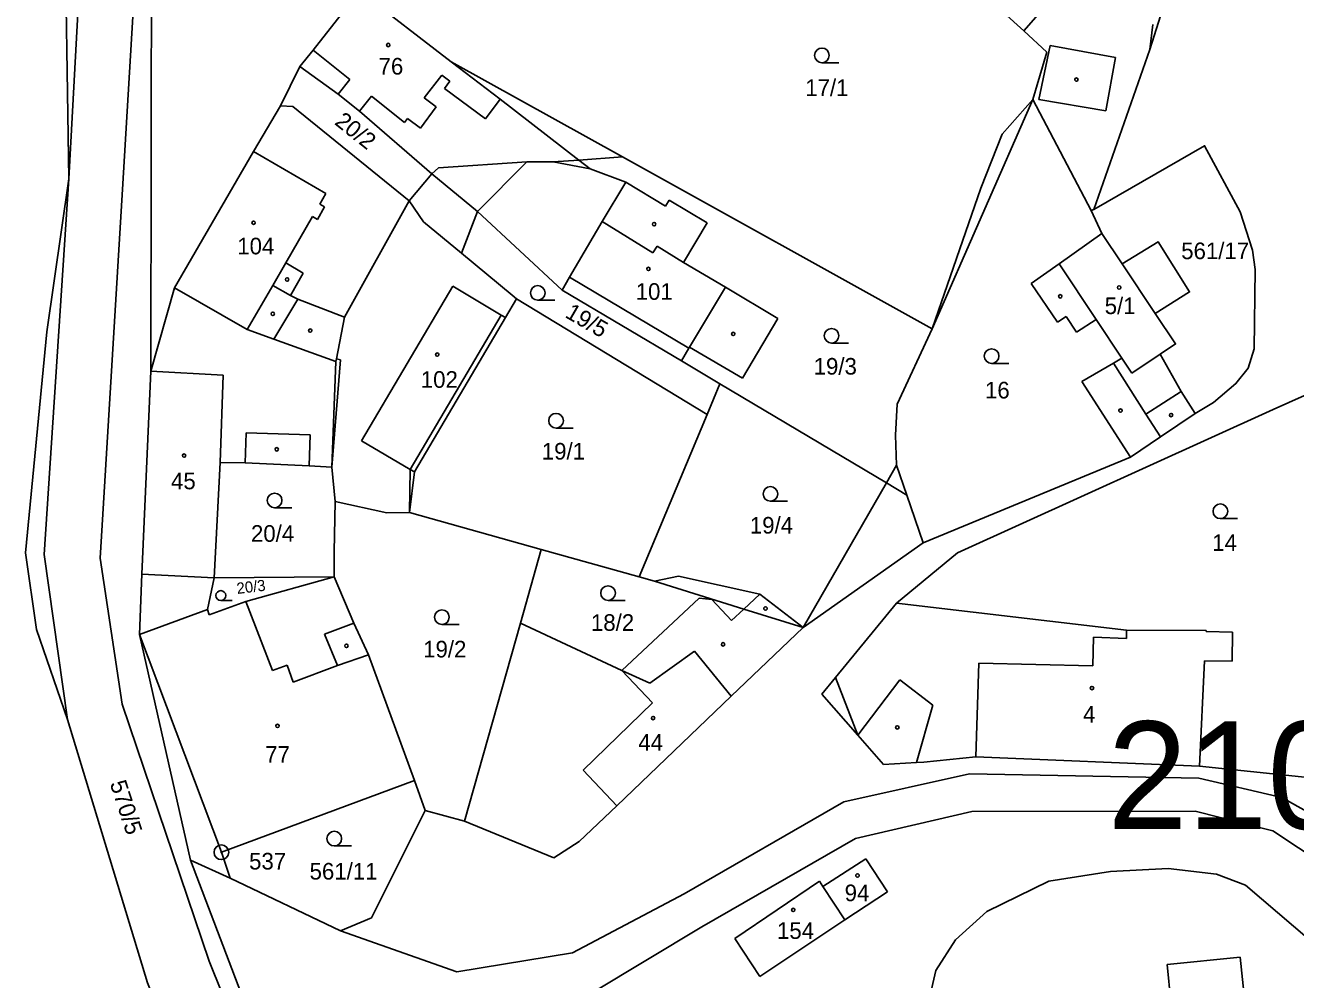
# Model space of a CAD drawing. Extents: x -725765 to -723182, y -1052705 to -1049154.
# Drawn here: x -724819.6 to -724689.6, y -1050869.4 to -1050771.8 of the extents above; entities that cross this region are included whole.
import ezdxf

# ---------------------------------------------------------------- set-up
doc = ezdxf.new("R2010")
doc.units = 0
for name, color, linetype in [('Vrstva 1', 7, 'Continuous'), ('Vrstva 17', 7, 'Continuous'), ('Vrstva 18', 7, 'Continuous'), ('Vrstva 19', 7, 'Continuous'), ('Vrstva 25', 7, 'Continuous'), ('Vrstva 4', 7, 'Continuous'), ('Vrstva 52', 7, 'Continuous'), ('Vrstva 53', 7, 'Continuous')]:
    doc.layers.add(name, color=color, linetype=linetype)

msp = doc.modelspace()

# ---------------------------------------------------------------- linework, layer by layer
at = {"layer": 'Vrstva 1'}
for points in [[(-724815.58, -1050758.85), (-724815.13, -1050787.45)], [(-724728.86, -1050761.96), (-724717.41, -1050772.31)], [(-724806.76, -1050807.12), (-724806.68, -1050763.03)], [(-724704.54, -1050774.22), (-724701.62, -1050765.05)], [(-724790.16, -1050774.29), (-724785.4, -1050768.2)], [(-724785.4, -1050768.2), (-724776.03, -1050775.48)], [(-724717.41, -1050772.31), (-724715.08, -1050774.5)], [(-724791.52, -1050775.96), (-724790.16, -1050774.29)], [(-724716.5, -1050779.33), (-724715.08, -1050774.5)], [(-724710.25, -1050790.58), (-724704.54, -1050774.22)], [(-724793.48, -1050779.98), (-724791.52, -1050775.96)], [(-724791.52, -1050775.96), (-724787.58, -1050778.77)], [(-724776.03, -1050775.48), (-724758.5, -1050785.2)], [(-724787.58, -1050778.77), (-724785.41, -1050780.52)], [(-724796.25, -1050784.66), (-724793.48, -1050779.98)], [(-724793.48, -1050779.98), (-724792.22, -1050780.03)], [(-724792.22, -1050780.03), (-724780.32, -1050789.71)], [(-724726.79, -1050802.8), (-724716.5, -1050779.33)], [(-724716.5, -1050779.33), (-724710.52, -1050790.67)], [(-724785.41, -1050780.52), (-724778, -1050786.94)], [(-724710.25, -1050790.58), (-724698.92, -1050784.06)], [(-724698.92, -1050784.06), (-724695.3, -1050790.82)], [(-724804.34, -1050798.59), (-724796.25, -1050784.66)], [(-724762.96, -1050785.53), (-724758.5, -1050785.2)], [(-724758.5, -1050785.2), (-724726.79, -1050802.8)], [(-724778, -1050786.94), (-724777.32, -1050786.32)], [(-724777.32, -1050786.32), (-724768.27, -1050785.71)], [(-724768.27, -1050785.71), (-724765.6, -1050785.72)], [(-724765.6, -1050785.72), (-724762.96, -1050785.53)], [(-724817.4, -1050803.09), (-724815.13, -1050787.45)], [(-724780.32, -1050789.71), (-724778, -1050786.94)], [(-724778, -1050786.94), (-724773.32, -1050790.79)], [(-724786.93, -1050801.6), (-724780.32, -1050789.71)], [(-724780.32, -1050789.71), (-724778.87, -1050791.83)], [(-724710.52, -1050790.67), (-724710.25, -1050790.58)], [(-724710.52, -1050790.67), (-724709.43, -1050793.04)], [(-724778.87, -1050791.83), (-724774.96, -1050795.04)], [(-724773.32, -1050790.79), (-724764.68, -1050798.83)], [(-724763.91, -1050797.52), (-724760.56, -1050791.82)], [(-724760.56, -1050791.82), (-724755.37, -1050795.02)], [(-724695.3, -1050790.82), (-724694.03, -1050794.75)], [(-724713.82, -1050796.14), (-724709.43, -1050793.04)], [(-724709.43, -1050793.04), (-724707.37, -1050796.13)], [(-724755.37, -1050795.02), (-724754.95, -1050794.32)], [(-724754.95, -1050794.32), (-724752.24, -1050795.99)], [(-724707.37, -1050796.13), (-724703.67, -1050793.89)], [(-724703.67, -1050793.89), (-724700.46, -1050799.01)], [(-724774.96, -1050795.04), (-724769.79, -1050799.33)], [(-724694.03, -1050794.75), (-724693.75, -1050796.73)], [(-724752.24, -1050795.99), (-724747.96, -1050798.54)], [(-724716.67, -1050798.15), (-724713.82, -1050796.14)], [(-724693.85, -1050804.82), (-724693.75, -1050796.73)], [(-724764.68, -1050798.83), (-724763.91, -1050797.52)], [(-724716.67, -1050798.15), (-724713.98, -1050802.11)], [(-724806.76, -1050807.12), (-724804.34, -1050798.59)], [(-724804.34, -1050798.59), (-724796.91, -1050802.85)], [(-724770.47, -1050801.64), (-724769.33, -1050799.71)], [(-724769.79, -1050799.33), (-724769.33, -1050799.71)], [(-724769.33, -1050799.71), (-724749.83, -1050811.55)], [(-724764.68, -1050798.83), (-724752.45, -1050806.06)], [(-724751.62, -1050804.67), (-724747.96, -1050798.54)], [(-724703.97, -1050801.23), (-724700.46, -1050799.01)], [(-724787.77, -1050805.86), (-724786.93, -1050801.6)], [(-724779.79, -1050817.43), (-724770.47, -1050801.64)], [(-724713.98, -1050802.11), (-724713.08, -1050801.52)], [(-724713.08, -1050801.52), (-724712.03, -1050803.14)], [(-724712.03, -1050803.14), (-724710.03, -1050801.83)], [(-724710.03, -1050801.83), (-724707.39, -1050805.79)], [(-724703.97, -1050801.23), (-724701.9, -1050804.33)], [(-724819.59, -1050825.69), (-724817.4, -1050803.09)], [(-724796.91, -1050802.85), (-724794.18, -1050803.83)], [(-724730.4, -1050810.48), (-724726.79, -1050802.8)], [(-724794.18, -1050803.83), (-724787.82, -1050806.12)], [(-724752.45, -1050806.06), (-724751.69, -1050804.78)], [(-724751.69, -1050804.78), (-724751.62, -1050804.67)], [(-724703.46, -1050805.38), (-724701.9, -1050804.33)], [(-724694.47, -1050806.81), (-724693.85, -1050804.82)], [(-724788.22, -1050816.94), (-724787.82, -1050806.12)], [(-724787.82, -1050806.12), (-724787.77, -1050805.86)], [(-724752.45, -1050806.06), (-724748.52, -1050808.4)], [(-724708.25, -1050806.29), (-724707.39, -1050805.79)], [(-724703.46, -1050805.38), (-724701.33, -1050809.2)], [(-724807.68, -1050827.87), (-724806.76, -1050807.12)], [(-724711.49, -1050808.16), (-724708.25, -1050806.29)], [(-724695.72, -1050808.39), (-724694.47, -1050806.81)], [(-724749.83, -1050811.55), (-724748.52, -1050808.4)], [(-724748.52, -1050808.4), (-724731.49, -1050818.54)], [(-724711.49, -1050808.16), (-724706.52, -1050815.92)], [(-724698, -1050810.32), (-724695.72, -1050808.39)], [(-724691.91, -1050811.03), (-724684.21, -1050807.61)], [(-724701.33, -1050809.2), (-724699.88, -1050811.44)], [(-724730.57, -1050813.66), (-724730.4, -1050810.48)], [(-724724.22, -1050825.7), (-724691.91, -1050811.03)], [(-724703.45, -1050813.85), (-724699.88, -1050811.44)], [(-724699.88, -1050811.44), (-724698, -1050810.32)], [(-724756.78, -1050828.16), (-724749.83, -1050811.55)], [(-724730.57, -1050813.66), (-724730.44, -1050816.72)], [(-724706.52, -1050815.92), (-724703.45, -1050813.85)], [(-724800.28, -1050828.24), (-724799.66, -1050816.47)], [(-724799.66, -1050816.47), (-724797.11, -1050816.51)], [(-724797.11, -1050816.51), (-724790.55, -1050816.79)], [(-724727.72, -1050824.69), (-724706.52, -1050815.92)], [(-724790.55, -1050816.79), (-724788.22, -1050816.94)], [(-724788.22, -1050816.94), (-724787.89, -1050820.45)], [(-724780.28, -1050821.58), (-724779.79, -1050817.43)], [(-724730.44, -1050816.72), (-724729.39, -1050819.79)], [(-724731.49, -1050818.54), (-724729.39, -1050819.79)], [(-724788, -1050825.59), (-724787.89, -1050820.45)], [(-724787.89, -1050820.45), (-724782.62, -1050821.61)], [(-724729.39, -1050819.79), (-724727.72, -1050824.69)], [(-724782.62, -1050821.61), (-724780.28, -1050821.58)], [(-724780.28, -1050821.58), (-724766.81, -1050825.35)], [(-724819.59, -1050825.69), (-724818.46, -1050833.53)], [(-724788.01, -1050828.17), (-724788, -1050825.59)], [(-724768.94, -1050832.9), (-724766.81, -1050825.35)], [(-724766.81, -1050825.35), (-724756.78, -1050828.16)], [(-724740.01, -1050833.33), (-724727.72, -1050824.69)], [(-724730.44, -1050830.86), (-724724.22, -1050825.7)], [(-724807.91, -1050834.06), (-724807.68, -1050827.87)], [(-724800.97, -1050831.5), (-724800.28, -1050828.24)], [(-724800.28, -1050828.24), (-724788.01, -1050828.17)], [(-724797.04, -1050830.69), (-724788.01, -1050828.17)], [(-724788.01, -1050828.17), (-724785.98, -1050832.9)], [(-724756.78, -1050828.16), (-724755.22, -1050828.6)], [(-724755.22, -1050828.6), (-724746.07, -1050831.45)], [(-724800.77, -1050832.05), (-724797.04, -1050830.69)], [(-724736.71, -1050838.46), (-724730.44, -1050830.86)], [(-724730.44, -1050830.86), (-724706.93, -1050833.62)], [(-724807.91, -1050834.06), (-724800.97, -1050831.5)], [(-724800.97, -1050831.5), (-724800.77, -1050832.05)], [(-724746.07, -1050831.45), (-724740.01, -1050833.33)], [(-724818.46, -1050833.53), (-724815.27, -1050842.75)], [(-724785.98, -1050832.9), (-724784.48, -1050836.14)], [(-724774.65, -1050853.16), (-724768.94, -1050832.9)], [(-724768.94, -1050832.9), (-724758.55, -1050837.73)], [(-724747.36, -1050840.36), (-724740.01, -1050833.33)], [(-724807.91, -1050834.06), (-724802.7, -1050857.13)], [(-724807.91, -1050834.06), (-724799.54, -1050856.33)], [(-724706.93, -1050833.62), (-724698.75, -1050833.66)], [(-724698.75, -1050833.66), (-724698.75, -1050833.76)], [(-724698.75, -1050833.76), (-724696.08, -1050833.83)], [(-724696.12, -1050836.78), (-724696.08, -1050833.83)], [(-724784.48, -1050836.14), (-724779.79, -1050849)], [(-724755.68, -1050839.02), (-724751.12, -1050835.77)], [(-724751.12, -1050835.77), (-724747.36, -1050840.36)], [(-724699.44, -1050847.52), (-724698.92, -1050836.75)], [(-724698.92, -1050836.75), (-724696.12, -1050836.78)], [(-724758.55, -1050837.73), (-724755.68, -1050839.02)], [(-724738.11, -1050840.16), (-724736.71, -1050838.46)], [(-724759.08, -1050851.58), (-724747.36, -1050840.36)], [(-724738.11, -1050840.16), (-724734.4, -1050844.36)], [(-724815.27, -1050842.75), (-724807.1, -1050869.67)], [(-724734.4, -1050844.36), (-724731.77, -1050847.34)], [(-724727.64, -1050847.12), (-724722.35, -1050846.57)], [(-724722.35, -1050846.57), (-724699.44, -1050847.52)], [(-724731.77, -1050847.34), (-724728.41, -1050847.16)], [(-724728.41, -1050847.16), (-724727.64, -1050847.12)], [(-724699.44, -1050847.52), (-724683.14, -1050849.22)], [(-724799.54, -1050856.33), (-724779.79, -1050849)], [(-724779.79, -1050849), (-724778.67, -1050852.04)], [(-724762.92, -1050855.21), (-724759.08, -1050851.58)], [(-724784.19, -1050863.03), (-724778.67, -1050852.04)], [(-724778.67, -1050852.04), (-724774.65, -1050853.16)], [(-724774.65, -1050853.16), (-724765.52, -1050856.89)], [(-724765.52, -1050856.89), (-724762.92, -1050855.21)], [(-724799.54, -1050856.33), (-724798.63, -1050858.99)], [(-724802.7, -1050857.13), (-724793.87, -1050880.36)], [(-724737.98, -1050859.82), (-724733.58, -1050857.01)], [(-724733.58, -1050857.01), (-724731.37, -1050860.36)], [(-724708.57, -1050858.29), (-724702.67, -1050857.98)], [(-724702.67, -1050857.98), (-724697.7, -1050858.58)], [(-724798.63, -1050858.99), (-724787.36, -1050864.36)], [(-724747, -1050865.14), (-724738.33, -1050859.3)], [(-724738.33, -1050859.3), (-724737.98, -1050859.82)], [(-724721.2, -1050862.37), (-724714.88, -1050859.27)], [(-724714.88, -1050859.27), (-724708.57, -1050858.29)], [(-724697.7, -1050858.58), (-724694.75, -1050859.69)], [(-724737.98, -1050859.82), (-724735.73, -1050863.25)], [(-724735.73, -1050863.25), (-724731.37, -1050860.36)], [(-724694.75, -1050859.69), (-724688.19, -1050865.28)], [(-724787.36, -1050864.36), (-724784.19, -1050863.03)], [(-724744.43, -1050869.03), (-724735.73, -1050863.25)], [(-724724.4, -1050865.28), (-724721.2, -1050862.37)], [(-724747, -1050865.14), (-724744.43, -1050869.03)], [(-724726.42, -1050868.43), (-724724.4, -1050865.28)], [(-724702.77, -1050867.8), (-724695.28, -1050867.04)], [(-724695.28, -1050867.04), (-724694.82, -1050871.61)], [(-724727.89, -1050874.8), (-724726.42, -1050868.43)], [(-724702.77, -1050867.8), (-724702.38, -1050871.62)]]:
    msp.add_lwpolyline(points, dxfattribs=at)
at = {"layer": 'Vrstva 25'}
for points in [[(-724738.09, -1050775.57), (-724736.34, -1050775.57)], [(-724767.16, -1050799.86), (-724765.41, -1050799.86)], [(-724737.1, -1050804.25), (-724735.35, -1050804.25)], [(-724720.72, -1050806.33), (-724718.97, -1050806.33)], [(-724765.29, -1050812.94), (-724763.54, -1050812.94)], [(-724743.35, -1050820.42), (-724741.6, -1050820.42)], [(-724794.09, -1050821.09), (-724792.34, -1050821.09)], [(-724697.31, -1050822.2), (-724695.56, -1050822.2)], [(-724799.59, -1050830.57), (-724798.42, -1050830.57)], [(-724759.97, -1050830.57), (-724758.22, -1050830.57)], [(-724776.97, -1050833.03), (-724775.22, -1050833.03)], [(-724787.98, -1050855.68), (-724786.23, -1050855.68)]]:
    msp.add_lwpolyline(points, dxfattribs=at)
for centre, radius in [((-724782.46, -1050773.76), 0.175), ((-724738.09, -1050774.82), 0.75), ((-724712.04, -1050777.29), 0.175), ((-724796.24, -1050791.94), 0.175), ((-724755.26, -1050792.08), 0.175), ((-724755.84, -1050796.66), 0.175), ((-724792.81, -1050797.74), 0.175), ((-724767.16, -1050799.11), 0.75), ((-724707.67, -1050798.56), 0.175), ((-724713.7, -1050799.46), 0.175), ((-724794.28, -1050801.25), 0.175), ((-724790.44, -1050802.97), 0.175), ((-724747.16, -1050803.31), 0.175), ((-724737.1, -1050803.5), 0.75), ((-724720.72, -1050805.58), 0.75), ((-724777.45, -1050805.42), 0.175), ((-724765.29, -1050812.19), 0.75), ((-724707.53, -1050811.15), 0.175), ((-724702.36, -1050811.61), 0.175), ((-724793.87, -1050815.11), 0.175), ((-724803.35, -1050815.75), 0.175), ((-724743.35, -1050819.67), 0.75), ((-724794.09, -1050820.34), 0.75), ((-724697.31, -1050821.45), 0.75), ((-724799.59, -1050830.07), 0.503), ((-724759.97, -1050829.82), 0.75), ((-724776.97, -1050832.28), 0.75), ((-724743.86, -1050831.39), 0.175), ((-724786.74, -1050835.21), 0.175), ((-724748.2, -1050835.06), 0.175), ((-724710.45, -1050839.53), 0.175), ((-724755.36, -1050842.6), 0.175), ((-724793.79, -1050843.4), 0.175), ((-724730.37, -1050843.56), 0.175), ((-724787.98, -1050854.93), 0.75), ((-724799.54, -1050856.33), 0.75), ((-724799.54, -1050856.33), 0.032), ((-724734.44, -1050858.7), 0.175), ((-724741.02, -1050862.22), 0.175)]:
    msp.add_circle(centre, radius, dxfattribs=at)
at = {"layer": 'Vrstva 4'}
for points in [[(-724815.13, -1050787.45), (-724813.82, -1050762.96)], [(-724809.63, -1050787.94), (-724808.16, -1050763.42)], [(-724717.41, -1050772.31), (-724712.35, -1050766.47)], [(-724704.54, -1050774.22), (-724704.24, -1050771.67)], [(-724790.16, -1050774.29), (-724786.39, -1050777.27)], [(-724715.89, -1050779.34), (-724714.74, -1050773.81)], [(-724714.74, -1050773.81), (-724708.03, -1050775.05)], [(-724709.02, -1050780.49), (-724708.03, -1050775.05)], [(-724776.03, -1050775.48), (-724771, -1050779.29)], [(-724787.58, -1050778.77), (-724786.39, -1050777.27)], [(-724778.79, -1050779.15), (-724776.97, -1050776.85)], [(-724776.97, -1050776.85), (-724776.16, -1050777.47)], [(-724776.71, -1050778.22), (-724776.16, -1050777.47)], [(-724776.71, -1050778.22), (-724772.51, -1050781.3)], [(-724785.41, -1050780.52), (-724784.18, -1050778.99)], [(-724784.18, -1050778.99), (-724780.79, -1050781.69)], [(-724779.17, -1050782.27), (-724777.57, -1050780.09)], [(-724778.79, -1050779.15), (-724777.57, -1050780.09)], [(-724772.51, -1050781.3), (-724771, -1050779.29)], [(-724771, -1050779.29), (-724762.96, -1050785.53)], [(-724719.63, -1050782.88), (-724716.5, -1050779.33)], [(-724715.89, -1050779.34), (-724709.02, -1050780.49)], [(-724780.79, -1050781.69), (-724780.48, -1050781.29)], [(-724780.48, -1050781.29), (-724779.17, -1050782.27)], [(-724721.83, -1050788.39), (-724719.63, -1050782.88)], [(-724796.25, -1050784.66), (-724788.85, -1050788.94)], [(-724773.32, -1050790.79), (-724768.27, -1050785.71)], [(-724765.6, -1050785.72), (-724761.79, -1050786.43)], [(-724762.96, -1050785.53), (-724761.79, -1050786.43)], [(-724761.79, -1050786.43), (-724758.14, -1050787.79)], [(-724817.68, -1050825.87), (-724815.13, -1050787.45)], [(-724811.93, -1050826.26), (-724809.63, -1050787.94)], [(-724760.56, -1050791.82), (-724758.14, -1050787.79)], [(-724758.14, -1050787.79), (-724754.1, -1050790.24)], [(-724789.47, -1050790.02), (-724788.85, -1050788.94)], [(-724726.79, -1050802.8), (-724721.83, -1050788.39)], [(-724789.71, -1050791.59), (-724788.99, -1050790.3)], [(-724789.47, -1050790.02), (-724788.99, -1050790.3)], [(-724754.1, -1050790.24), (-724753.72, -1050789.62)], [(-724753.72, -1050789.62), (-724749.83, -1050791.94)], [(-724792.93, -1050796.04), (-724790.2, -1050791.29)], [(-724790.2, -1050791.29), (-724789.71, -1050791.59)], [(-724774.96, -1050795.04), (-724773.32, -1050790.79)], [(-724752.24, -1050795.99), (-724749.83, -1050791.94)], [(-724794.27, -1050798.37), (-724792.93, -1050796.04)], [(-724792.93, -1050796.04), (-724791.16, -1050797.08)], [(-724792.48, -1050799.37), (-724791.16, -1050797.08)], [(-724713.82, -1050796.14), (-724710.03, -1050801.83)], [(-724707.37, -1050796.13), (-724703.97, -1050801.23)], [(-724796.91, -1050802.85), (-724794.27, -1050798.37)], [(-724794.27, -1050798.37), (-724792.48, -1050799.37)], [(-724785.19, -1050814.23), (-724775.86, -1050798.44)], [(-724775.86, -1050798.44), (-724770.9, -1050801.39)], [(-724763.91, -1050797.52), (-724751.69, -1050804.78)], [(-724794.18, -1050803.83), (-724791.73, -1050799.77)], [(-724792.48, -1050799.37), (-724791.73, -1050799.77)], [(-724791.73, -1050799.77), (-724786.93, -1050801.6)], [(-724747.96, -1050798.54), (-724742.61, -1050801.73)], [(-724780.22, -1050817.18), (-724770.9, -1050801.39)], [(-724770.9, -1050801.39), (-724770.47, -1050801.64)], [(-724746.22, -1050807.85), (-724742.61, -1050801.73)], [(-724751.62, -1050804.67), (-724746.22, -1050807.85)], [(-724788.22, -1050816.94), (-724787.35, -1050805.95)], [(-724787.77, -1050805.86), (-724787.35, -1050805.95)], [(-724707.39, -1050805.79), (-724706.37, -1050807.33)], [(-724706.37, -1050807.33), (-724703.46, -1050805.38)], [(-724806.76, -1050807.12), (-724799.34, -1050807.54)], [(-724799.66, -1050816.47), (-724799.34, -1050807.54)], [(-724708.25, -1050806.29), (-724704.94, -1050811.51)], [(-724704.94, -1050811.51), (-724701.33, -1050809.2)], [(-724704.94, -1050811.51), (-724703.45, -1050813.85)], [(-724797.11, -1050816.51), (-724797, -1050813.43)], [(-724797, -1050813.43), (-724790.45, -1050813.64)], [(-724790.55, -1050816.79), (-724790.45, -1050813.64)], [(-724785.19, -1050814.23), (-724780.22, -1050817.18)], [(-724780.28, -1050821.58), (-724780.22, -1050817.18)], [(-724780.22, -1050817.18), (-724779.79, -1050817.43)], [(-724731.49, -1050818.54), (-724730.44, -1050816.72)], [(-724740.01, -1050833.33), (-724731.49, -1050818.54)], [(-724817.68, -1050825.87), (-724815.27, -1050842.75)], [(-724811.93, -1050826.26), (-724809.69, -1050841.19)], [(-724807.68, -1050827.87), (-724800.28, -1050828.24)], [(-724755.22, -1050828.6), (-724752.75, -1050828.08)], [(-724752.75, -1050828.08), (-724744.44, -1050829.94)], [(-724797.04, -1050830.69), (-724794.32, -1050837.75)], [(-724758.55, -1050837.73), (-724750.66, -1050830.33)], [(-724750.66, -1050830.33), (-724749.36, -1050830.47)], [(-724749.36, -1050830.47), (-724747.34, -1050832.62)], [(-724746.07, -1050831.45), (-724744.44, -1050829.94)], [(-724744.44, -1050829.94), (-724740.01, -1050833.33)], [(-724747.34, -1050832.62), (-724746.07, -1050831.45)], [(-724788.97, -1050834.02), (-724785.98, -1050832.9)], [(-724788.97, -1050834.02), (-724787.67, -1050837.24)], [(-724710.37, -1050837.27), (-724710.3, -1050834.34)], [(-724710.3, -1050834.34), (-724706.93, -1050834.47)], [(-724706.93, -1050834.47), (-724706.93, -1050833.62)], [(-724787.67, -1050837.24), (-724784.48, -1050836.14)], [(-724794.32, -1050837.75), (-724792.82, -1050837.2)], [(-724792.82, -1050837.2), (-724792.19, -1050838.93)], [(-724792.19, -1050838.93), (-724787.67, -1050837.24)], [(-724722.35, -1050846.57), (-724722.04, -1050837)], [(-724722.04, -1050837), (-724710.37, -1050837.27)], [(-724758.55, -1050837.73), (-724755.41, -1050841.05)], [(-724736.71, -1050838.46), (-724734.4, -1050844.36)], [(-724734.4, -1050844.36), (-724730.12, -1050838.69)], [(-724730.12, -1050838.69), (-724726.72, -1050841.29)], [(-724809.69, -1050841.19), (-724800.77, -1050867.46)], [(-724762.53, -1050847.92), (-724755.41, -1050841.05)], [(-724728.41, -1050847.16), (-724726.72, -1050841.29)], [(-724762.53, -1050847.92), (-724759.08, -1050851.58)], [(-724735.84, -1050851.18), (-724722.97, -1050848.3)], [(-724722.97, -1050848.3), (-724699.53, -1050848.74)], [(-724699.53, -1050848.74), (-724691.02, -1050850.72)], [(-724752.19, -1050860.57), (-724735.84, -1050851.18)], [(-724691.02, -1050850.72), (-724683.3, -1050855.06)], [(-724734.65, -1050854.92), (-724722.73, -1050852.15)], [(-724722.73, -1050852.15), (-724699.9, -1050852.11)], [(-724699.9, -1050852.11), (-724691.95, -1050854.12)], [(-724691.95, -1050854.12), (-724686.7, -1050857.6)], [(-724750.38, -1050863.96), (-724734.65, -1050854.92)], [(-724802.7, -1050857.13), (-724798.63, -1050858.99)], [(-724763.6, -1050866.6), (-724752.19, -1050860.57)], [(-724787.36, -1050864.36), (-724775.43, -1050868.55)], [(-724761.65, -1050870.74), (-724750.38, -1050863.96)], [(-724775.43, -1050868.55), (-724763.6, -1050866.6)], [(-724800.77, -1050867.46), (-724786.35, -1050903.34)]]:
    msp.add_lwpolyline(points, dxfattribs=at)
at = {"layer": 'Vrstva 52'}
for points in [[(-724813.33, -1050644), (-724808.37, -1050650.73), (-724806.43, -1050654.63), (-724804.75, -1050661.51), (-724810.21, -1050691.79), (-724815, -1050731.09), (-724815.58, -1050758.85), (-724815.13, -1050787.45), (-724817.4, -1050803.09), (-724819.59, -1050825.69), (-724818.46, -1050833.53), (-724815.27, -1050842.75), (-724807.1, -1050869.67), (-724799.84, -1050887.62), (-724790.58, -1050905.75), (-724781.27, -1050921.4), (-724774.72, -1050931.91), (-724769.97, -1050937.91), (-724755.76, -1050950.09), (-724747.39, -1050955.27), (-724740.23, -1050960.06), (-724733.48, -1050964.31), (-724729, -1050967.94)], [(-724797.81, -1050648.79), (-724786.08, -1050660.92), (-724787.52, -1050665.42), (-724789.04, -1050670.2), (-724789.99, -1050673.16), (-724795.12, -1050673.64), (-724798.75, -1050677.64), (-724800.93, -1050691.71), (-724804.92, -1050728), (-724806.68, -1050763.03), (-724806.76, -1050807.12), (-724807.68, -1050827.87), (-724807.91, -1050834.06), (-724802.7, -1050857.13), (-724793.87, -1050880.36), (-724784.64, -1050902.78), (-724767.07, -1050925.79), (-724749.83, -1050943.31), (-724735.73, -1050952.08), (-724724.93, -1050961.09)], [(-724701.33, -1050809.2), (-724699.88, -1050811.44), (-724698, -1050810.32), (-724695.72, -1050808.39), (-724694.47, -1050806.81), (-724693.85, -1050804.82), (-724693.75, -1050796.73), (-724694.03, -1050794.75), (-724695.3, -1050790.82), (-724698.92, -1050784.06), (-724710.25, -1050790.58), (-724710.52, -1050790.67), (-724709.43, -1050793.04), (-724707.37, -1050796.13), (-724703.67, -1050793.89), (-724700.46, -1050799.01), (-724703.97, -1050801.23), (-724701.9, -1050804.33), (-724703.46, -1050805.38), (-724701.33, -1050809.2)]]:
    msp.add_lwpolyline(points, dxfattribs=at)

# ---------------------------------------------------------------- texts
at = {"layer": 'Vrstva 17'}
msp.add_text('537', height=1.7, dxfattribs=at).set_placement((-724796.7, -1050858.09))
at = {"layer": 'Vrstva 18'}
for s, p in [('17/1', (-724739.79, -1050778.97)), ('561/17', (-724701.32, -1050795.66)), ('19/3', (-724738.93, -1050807.47)), ('16', (-724721.4, -1050809.91)), ('19/1', (-724766.75, -1050816.16)), ('20/4', (-724796.51, -1050824.57)), ('19/4', (-724745.46, -1050823.73)), ('14', (-724698.15, -1050825.5)), ('18/2', (-724761.72, -1050833.68)), ('19/2', (-724778.89, -1050836.4)), ('561/11', (-724790.51, -1050859.12))]:
    msp.add_text(s, height=1.7, dxfattribs=at).set_placement(p)
for s, height, rotation, p in [('20/2', 1.7, 321.4026, (-724788.05, -1050781.8)), ('19/5', 1.7, 330.0026, (-724764.47, -1050801.55)), ('20/3', 1.14, 6.7001, (-724797.91, -1050829.91)), ('570/5', 1.7, 288.2023, (-724810.97, -1050849.28))]:
    msp.add_text(s, height=height, rotation=rotation, dxfattribs=at).set_placement(p)
at = {"layer": 'Vrstva 19'}
for s, p in [('76', (-724783.45, -1050776.78)), ('104', (-724797.91, -1050795.17)), ('101', (-724757.14, -1050799.82)), ('5/1', (-724709.15, -1050801.28)), ('102', (-724779.13, -1050808.82)), ('45', (-724804.69, -1050819.2)), ('4', (-724711.37, -1050843.06)), ('44', (-724756.87, -1050845.93)), ('77', (-724795.05, -1050847.17)), ('94', (-724735.76, -1050861.33)), ('154', (-724742.68, -1050865.19))]:
    msp.add_text(s, height=1.7, dxfattribs=at).set_placement(p)
at = {"layer": 'Vrstva 53'}
msp.add_text('21010', height=11, dxfattribs=at).set_placement((-724708.86, -1050853.94))

doc.saveas('drawing.dxf')
